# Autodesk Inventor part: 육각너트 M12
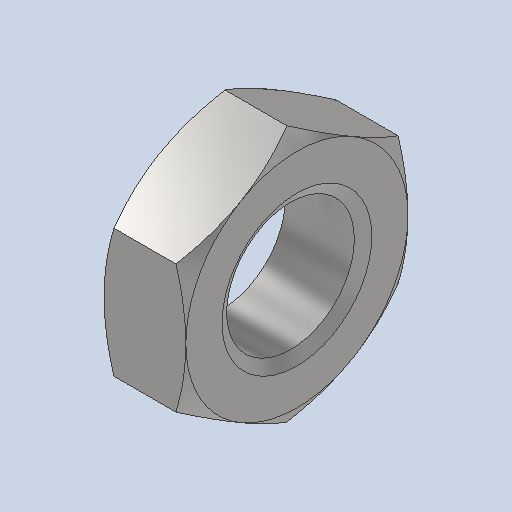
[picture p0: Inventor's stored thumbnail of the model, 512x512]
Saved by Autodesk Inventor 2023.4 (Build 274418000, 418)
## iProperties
Created: 2024-04
Part Number: 육각너트 M12
Material: 강철, 연강
Description: 6각 너트 및 6각 가는 너트
Document SubType Name: Modeling
Designer: Edu03
Density: 7.85 g/cm^3
Appearance: 기본값
Author: jhkim
Sending System: Autodesk Inventor 2025
Preprocessor: ST-DEVELOPER v20
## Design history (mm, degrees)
feature "Solid1"
node "솔리드1"
